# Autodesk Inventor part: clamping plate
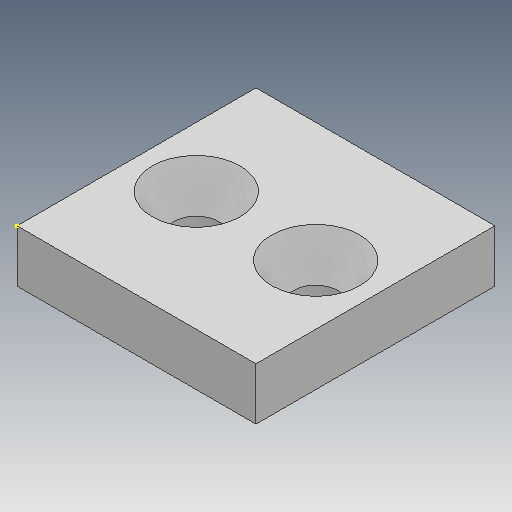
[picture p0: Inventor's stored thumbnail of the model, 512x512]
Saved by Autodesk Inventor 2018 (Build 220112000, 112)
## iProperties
Created: 2016-03
Part Number: clamping plate
Material: Generic
Document SubType Name: Modeling
Designer: Sandeep
Density: 1 g/cm^3
Appearance: Default
Author: Sandeep
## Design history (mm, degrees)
sketch "Sketch1"
  geometry: L1 (0, 0)-(32, 0); L2 (32, 0)-(32, 32); L3 (32, 32)-(0, 32); L4 (0, 32)-(0, 0)
  constraints: 8 end point, 2 parallel, 1 horizontal, 1 perpendicular
  dimensions: "d0" = 32 distance between parallel lines of L1 L3; "d1" = 32 distance of L2.end L3.end
extrude "Extrusion1" new body sketch "Sketch1" distance "d2" = 7; taper "d3" = 0 deg
sketch "Sketch2"
  geometry: 1 further point
sketch "Sketch3"
  geometry: 1 further point
hole "Hole2" diameter "d15" = 6; stored, may be unused: countersink angle "d19" = 60 deg, drill point angle "d21" = 118 deg; dims "d13" = 8, "d14" = 16, "d16" = 6, "d17" = 11.78, "d18" = 2, "d20" = 8
sketch "Sketch4"
  geometry: 1 further point
hole "Hole3" diameter "d24" = 6; stored, may be unused: countersink angle "d28" = 60 deg, drill point angle "d30" = 118 deg; dims "d22" = 8, "d23" = 16, "d25" = 6, "d26" = 11.78, "d27" = 2, "d29" = 8
body "Solid1"
